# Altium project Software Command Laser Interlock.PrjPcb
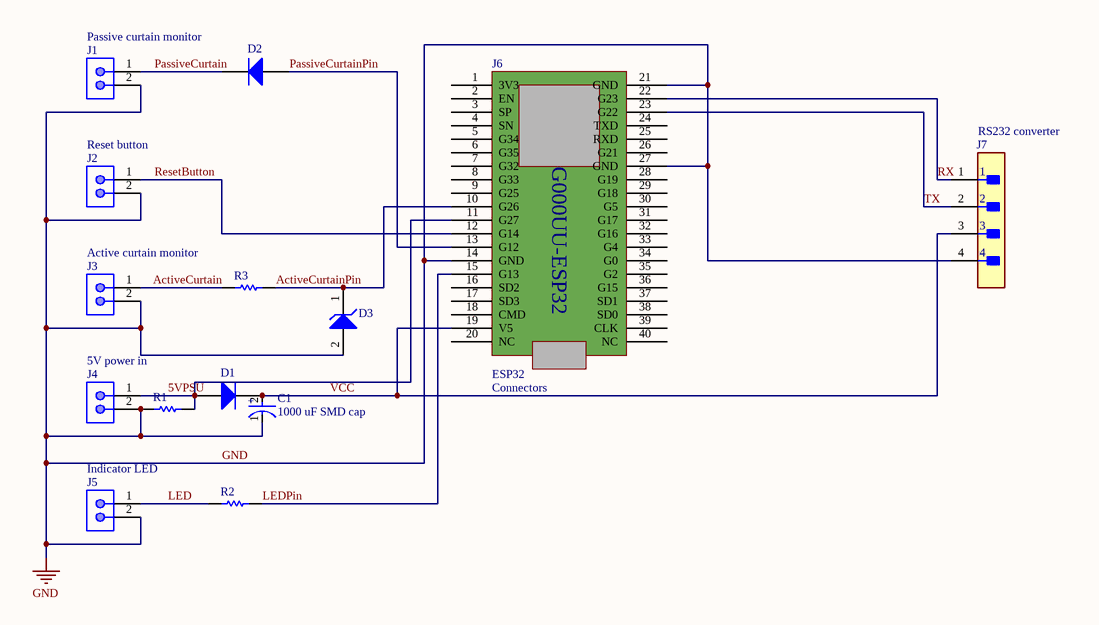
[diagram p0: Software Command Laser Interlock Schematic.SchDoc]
1 sheet, 14 parts. Net scope: global (net labels, ports and power ports of the same name join across sheets).
Board file: Software Command Laser Interlock PCB.PcbDoc

## Sheet Software Command Laser Interlock Schematic.SchDoc
size A4; SheetNumber: 1; SheetTotal: 1

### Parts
C1  1000 uF SMD cap  [1000 uF SMD Cap]
D1  1N4148W-7-F  [DIOD-SOD123-2_V]  (value not drawn)
D2  1N4148W-7-F  [DIOD-SOD123-2_V]  (value not drawn)
D3  MMSZ4688T1G  [ONSC-SOD-123-2-425-04_V]  (value not drawn)
J1  22-23-2021  [MOLX-22-23-2021_V]  (value not drawn)
J2  22-23-2021  [MOLX-22-23-2021_V]  (value not drawn)
J3  22-23-2021  [MOLX-22-23-2021_V]  (value not drawn)
J4  22-23-2021  [MOLX-22-23-2021_V]  (value not drawn)
J5  22-23-2021  [MOLX-22-23-2021_V]  (value not drawn)
J6  ESP32  Category: Connectors  [ESP32 Footprint]
J7  47053-1000  [FP-47053-1000-MFG]  (value not drawn)
R1  CRCW120610K0JNEA  [RESC3216X60X45ML10T20]  (value not drawn)
R2  CRCW1206150RFKEA  [RESC3216X60X45ML10T20]  (value not drawn)
R3  CRCW120610K0JNEA  [RESC3216X60X45ML10T20]  (value not drawn)

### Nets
GND: C1.1(C) D3.2(A) J1.2 J2.2 J3.2 J4.2 J5.2 J6.14(GND) J6.21(GND) J6.27(GND) J7.4 R1.1
5VPSU: D1.1(A) J4.1 J6.11(G27) R1.2
ActiveCurtain: J3.1 R3.1
ActiveCurtainPin: D3.1(K) J6.10(G26) R3.2
LED: J5.1 R2.1
LEDPin: J6.15(G13) R2.2
PassiveCurtain: D2.2(K) J1.1
PassiveCurtainPin: D2.1(A) J6.13(G12)
ResetButton: J2.1 J6.12(G14)
RX: J6.22(G23) J7.1
TX: J6.23(G22) J7.2
VCC: C1.2(A) D1.2(K) J6.19(V5) J7.3

Not connected (* = marked no-connect by the designer): J6 1(3V3) 2(EN) 3(SP) 4(SN) 5(G34) 6(G35) 7(G32) 8(G33) 9(G25) 16(SD2) 17(SD3) 18(CMD) 20(NC) 24(TXD) 25(RXD) 26(G21) 28(G19) 29(G18) 30(G5) 31(G17) 32(G16) 33(G4) 34(G0) 35(G2) 36(G15) 37(SD1) 38(SD0) 39(CLK) 40(NC)

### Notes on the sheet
- Passive curtain monitor
- (near J2) Reset button
- (near J7) RS232 converter
- Active curtain monitor
- 5V power in
- (near J5) Indicator LED

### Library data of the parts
C1 = 1000 uF SMD cap: https://uk.farnell.com/kemet/t523h108m010ape070/cap-1000-f-10v-20/dp/2913804
D1 D2 = CMP-2000-04932-2: Fast Switching Diode, 100 V, 0.15 A, -65 to 150 degC, 2-Pin?SOD123, RoHS, Tape and Reel; Recovery Time: 4ns; Brand: DiodesIncorporated; Unit Weight: 0.000353oz; Max Surge Current: 2A; Peak Reverse Voltage: 100V; Ir - Reverse Current: 1uA; Vf - Forward Voltage: 1.25V; Configuration: Single; If - Forward Current: 0.15A
D3 = CMP-1060-00561-1: Zener Voltage Regulator, 500 mW, 2-Pin SOD-123, Pb-Free, Tape and Reel; Manufacturer: On Semiconductor; VZ Typ (V): 4.7; P Max (W): 0.5
J1-J5 = CMP-1704-00001-3: Male Header, Pitch 2.54 mm, 1 x 2 Position, Height 10.67 mm, Tail Length 3.56 mm, 0 to 75 degC, RoHS, Bulk
J6 = ESP32: 2 x 1 row x 20 position header sockets to house the ESP32 DEV board
J7 = CMP-04776-000290-1: CONN HEADER VERT 4POS 2.54MM; Number of Positions: 4; Voltage Rating (DC): 250V; Gender: Male; Current Rating: 4A; Glow Wire Compliant: Non-compliant
R1 R3 = CMP-2003-04808-1: Manufacturer: Vishay Dale
R2 = CMP-2003-01812-1: Manufacturer: Vishay Dale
